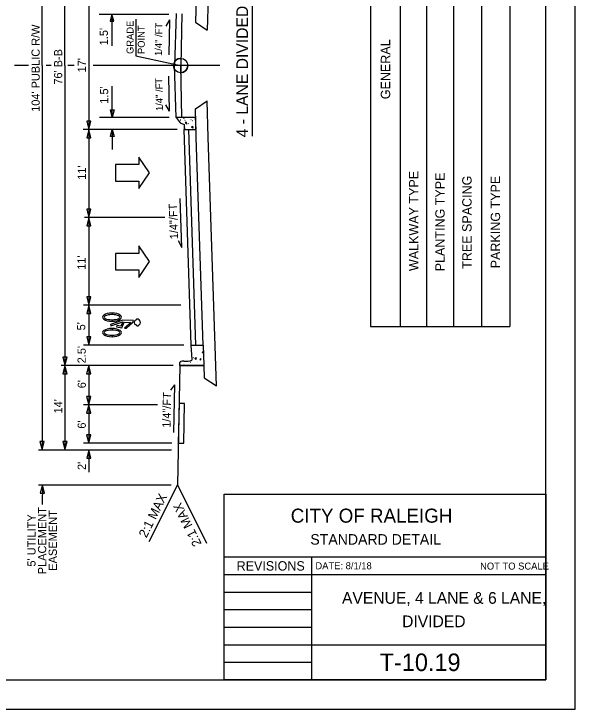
# Model space of a CAD drawing. Extents: x 0 to 8.5, y 0 to 11.
# Drawn here: x 3.7 to 8.5, y 0 to 5.94 of the extents above; entities that cross this region are included whole.
import ezdxf

# ---------------------------------------------------------------- set-up
doc = ezdxf.new("R2010")
doc.units = 0
for name, color, linetype in [('Level 2', 7, 'Continuous'), ('Level 21', 7, 'Continuous'), ('Level 22', 7, 'Continuous'), ('Level 23', 7, 'Continuous'), ('MARK BICYCLE SYMBOL CELL', 7, 'Continuous'), ('Old_Level_1', 7, 'Continuous'), ('Old_Level_11', 7, 'Continuous'), ('PROP LANE ARROW CELL', 7, 'Continuous'), ('Prop Shade Light', 7, 'Continuous'), ('SHEET BORDER', 7, 'Continuous'), ('SHEET NOTES', 7, 'Continuous'), ('SHEET TITLE BLOCK LINE', 7, 'Continuous'), ('SHEET TITLE BLOCK TEXT', 7, 'Continuous'), ('SHEET TRIM BORDER', 7, 'Continuous'), ('Typical Pavement Slope Information CELL', 7, 'Continuous')]:
    doc.layers.add(name, color=color, linetype=linetype)

msp = doc.modelspace()

# ---------------------------------------------------------------- linework, layer by layer
at = {"layer": 'Level 2'}
msp.add_line((5.7386, 6.0451), (5.7386, 4.8951), dxfattribs=at)
at = {"layer": 'Level 22'}
for p, q in [((5.1374, 5.9409), (5.1278, 5.5)), ((5.1319, 5.6877), (5.1319, 5.6877)), ((5.1319, 5.6877), (5.1319, 5.6877)), ((5.1278, 5.5611), (5.1278, 5.5)), ((5.1278, 5.5), (5.0667, 5.5)), ((5.1278, 5.5), (5.1278, 5.4389)), ((5.1889, 5.5), (5.1278, 5.5)), ((5.1374, 5.0591), (5.1278, 5.5)), ((5.1319, 5.3123), (5.1319, 5.3123))]:
    msp.add_line(p, q, dxfattribs=at)
msp.add_circle((5.1278, 5.4999), 0.0611, dxfattribs=at)
for start, end in [(90, 180), (270, 0)]:
    msp.add_arc((5.1278, 5.4999), 0.0611, start, end, dxfattribs=at)
at = {"layer": 'Level 23'}
for p, q in [((5.1388, 3.9439), (5.1241, 4.3629)), ((5.1064, 4.0057), (5.1388, 3.9439)), ((5.0738, 2.7708), (5.0411, 2.7251)), ((5.0738, 2.7708), (5.0657, 2.3647))]:
    msp.add_line(p, q, dxfattribs=at)
at = {"layer": 'MARK BICYCLE SYMBOL CELL'}
for p, q in [((4.5405, 3.3845), (4.5405, 3.3714)), ((4.5405, 3.3845), (4.5405, 3.3714)), ((4.5405, 3.3275), (4.5405, 3.3143)), ((4.5405, 3.3275), (4.5405, 3.3143)), ((4.7526, 3.3269), (4.7526, 3.3351)), ((4.7526, 3.3269), (4.7526, 3.3351)), ((4.6344, 3.325), (4.527, 3.2872)), ((4.527, 3.2872), (4.5299, 3.2747)), ((4.5312, 3.2751), (4.6324, 3.3107)), ((4.582, 3.2794), (4.5793, 3.2669)), ((4.6161, 3.2721), (4.582, 3.2794)), ((4.6324, 3.3107), (4.6161, 3.2721)), ((4.6237, 3.2574), (4.6449, 3.3077)), ((4.724, 3.3197), (4.6344, 3.325)), ((4.6449, 3.3077), (4.7035, 3.3042)), ((4.7035, 3.3042), (4.6483, 3.2547)), ((4.6649, 3.2547), (4.719, 3.3028)), ((4.719, 3.3028), (4.724, 3.3197)), ((4.7526, 3.2745), (4.7526, 3.2827)), ((4.7526, 3.2745), (4.7526, 3.2827)), ((4.5405, 3.2529), (4.5405, 3.2398)), ((4.5405, 3.2529), (4.5405, 3.2398)), ((4.5793, 3.2669), (4.6237, 3.2574)), ((4.6483, 3.2547), (4.6649, 3.2547)), ((4.5405, 3.1959), (4.5405, 3.1828)), ((4.5405, 3.1959), (4.5405, 3.1828))]:
    msp.add_line(p, q, dxfattribs=at)
for radius, start, end in [(0.0303, 270.00002, 90.00002), (0.0303, 270.00002, 90.00002), (0.0221, 90.00002, 270.00002)]:
    msp.add_arc((4.7526, 3.3048), radius, start, end, dxfattribs=at)
for centre, major_axis, ratio, start_param, end_param in [((4.5405, 3.3494), (-0.0804, 0), 0.435841, 4.712389, 7.853982), ((4.5405, 3.3494), (-0.0673, 0), 0.325967, 4.712389, 7.853982), ((4.5405, 3.3494), (-0.0804, 0), 0.435841, 1.570796, 4.712389), ((4.5405, 3.3494), (-0.0673, 0), 0.325967, 1.570796, 4.712389), ((4.5405, 3.2178), (-0.0804, 0), 0.435841, 4.712389, 7.853982), ((4.5405, 3.2178), (-0.0673, 0), 0.325967, 4.712389, 7.853982), ((4.5405, 3.2178), (-0.0804, 0), 0.435841, 1.570796, 4.712389), ((4.5405, 3.2178), (-0.0673, 0), 0.325967, 1.570796, 4.712389)]:
    msp.add_ellipse(centre, major_axis=major_axis, ratio=ratio, start_param=start_param, end_param=end_param, dxfattribs=at)
at = {"layer": 'Old_Level_1'}
for p, q in [((5.2612, 6.114), (5.2533, 5.8693)), ((5.3636, 6.114), (5.3535, 5.8025)), ((5.088, 5.9434), (5.0744, 5.4998)), ((5.2533, 5.8693), (5.3535, 5.8025)), ((5.088, 5.0561), (5.0744, 5.4998)), ((5.2533, 5.1302), (5.3535, 5.1971)), ((5.3636, 4.8855), (5.3535, 5.1971)), ((5.2612, 4.8855), (5.2533, 5.1302)), ((5.1251, 5.0306), (5.1222, 5.0312)), ((5.1268, 5.0364), (5.124, 5.037)), ((5.1651, 5.0312), (5.1622, 5.0315)), ((5.1948, 5.0041), (5.1928, 5.0032)), ((5.2165, 5.0353), (5.2136, 5.0353)), ((5.2308, 5.0278), (5.228, 5.0278)), ((5.2165, 3.111), (5.1566, 4.9538)), ((5.1655, 4.9615), (5.1633, 4.9624)), ((5.2575, 3.111), (5.1976, 4.9538)), ((5.3189, 3.111), (5.2612, 4.8855)), ((5.4326, 2.7623), (5.3636, 4.8855)), ((5.1545, 2.9745), (5.1912, 2.9749)), ((5.2403, 3.0021), (5.2381, 3.0023)), ((5.12, 2.9371), (5.0997, 1.9169)), ((5.12, 2.9366), (5.12, 2.9616)), ((5.3246, 2.9366), (5.12, 2.9366)), ((5.12, 2.9366), (5.1542, 2.9366)), ((5.1309, 2.969), (5.1299, 2.969)), ((5.1563, 2.9388), (5.1538, 2.9388)), ((5.1542, 2.9366), (5.3246, 2.9366)), ((5.2122, 2.9609), (5.2097, 2.9609)), ((5.2723, 2.9669), (5.2701, 2.9669)), ((5.3235, 2.969), (5.3216, 2.969)), ((5.3246, 2.9366), (5.3288, 2.8315)), ((5.3288, 2.8315), (5.4326, 2.7623)), ((5.0997, 1.9169), (4.856, 1.4295)), ((5.0997, 1.9169), (5.3491, 1.4179))]:
    msp.add_line(p, q, dxfattribs=at)
for points in [[(5.088, 5.0561), (5.1237, 5.0118), (5.1566, 4.9959), (5.1566, 4.9538), (5.259, 4.9538), (5.2557, 5.0561)], [(5.1781, 5.0125), (5.1656, 5.0131), (5.1789, 4.9995)], [(5.2303, 4.966), (5.2202, 4.9734), (5.2298, 4.9819)]]:
    msp.add_lwpolyline(points, close=True, dxfattribs=at)
for points in [[(5.1487, 5.0561), (5.1565, 5.0481), (5.156, 5.0561)], [(5.3189, 3.111), (5.3246, 2.9366), (5.1542, 2.9366), (5.12, 2.9366), (5.1201, 2.9616)], [(5.2256, 2.9883), (5.2165, 3.111), (5.3189, 3.111)], [(5.3212, 3.0412), (5.3122, 3.0478), (5.3207, 3.0554)], [(5.2579, 2.9868), (5.2485, 2.9954), (5.2591, 3.0053), (5.2579, 2.9868)], [(5.2999, 2.9856), (5.2985, 2.9968), (5.2921, 2.9873), (5.2999, 2.9856)], [(5.291, 2.9366), (5.2942, 2.9396), (5.294, 2.9366)]]:
    msp.add_lwpolyline(points, dxfattribs=at)
for centre, major_axis, start_param, end_param in [((5.1556, 2.9616), (-0.0356, 0), 4.744401, 6.283185), ((5.1901, 2.9878), (0.0356, 0), 4.744378, 6.315174)]:
    msp.add_ellipse(centre, major_axis=major_axis, ratio=0.362757, start_param=start_param, end_param=end_param, dxfattribs=at)
at = {"layer": 'Old_Level_11'}
for p, q in [((3.9424, 5.5), (3.9424, 8.7842)), ((4.1383, 5.5), (4.1383, 8.7842)), ((4.3431, 6.046), (4.3431, 4.954)), ((4.4319, 5.9404), (5.0271, 5.9404)), ((4.5396, 5.9404), (4.5396, 5.6694)), ((4.7441, 5.8968), (4.744, 5.5833)), ((4.744, 5.5833), (5.1271, 5.5017)), ((3.8261, 5.5), (3.7066, 5.5)), ((3.9424, 5.5), (3.9424, 2.2158)), ((4.0195, 5.5), (3.9777, 5.5)), ((4.1383, 5.5), (4.1383, 2.9369)), ((4.2162, 5.5), (4.1625, 5.5)), ((5.463, 5.5), (4.3792, 5.5)), ((4.5425, 5.0596), (4.5425, 5.3249)), ((4.4348, 5.0596), (5.0299, 5.0595)), ((4.1383, 4.954), (4.1383, 2.2158)), ((5.0972, 4.954), (4.2944, 4.954)), ((4.3431, 4.954), (4.3431, 4.2032)), ((4.5425, 4.954), (4.5425, 4.7816)), ((4.9935, 4.202), (4.3043, 4.202)), ((4.3431, 4.2032), (4.3431, 3.1112)), ((5.1299, 3.4525), (4.2981, 3.4525)), ((5.1547, 3.1112), (4.2972, 3.1112)), ((5.0638, 2.9369), (4.105, 2.9369)), ((4.3414, 2.9369), (4.3414, 2.5994)), ((4.9281, 2.5994), (4.2972, 2.5994)), ((4.3414, 2.5994), (4.3414, 2.2722)), ((5.0526, 2.2722), (4.2972, 2.2722)), ((3.9115, 2.2158), (5.0498, 2.2158)), ((4.3431, 2.2146), (4.3431, 2.0245)), ((3.9115, 1.9169), (5.0451, 1.9169)), ((3.9449, 1.9168), (3.9443, 1.7476))]:
    msp.add_line(p, q, dxfattribs=at)
for points in [[(4.555, 5.8788), (4.5396, 5.9404), (4.5242, 5.8788)], [(4.5579, 5.1211), (4.5425, 5.0596), (4.5271, 5.1211)], [(4.3254, 5.0248), (4.3431, 4.954), (4.3608, 5.0248)], [(4.3608, 4.8832), (4.3431, 4.954), (4.3254, 4.8832)], [(4.5271, 4.8924), (4.5425, 4.954), (4.5579, 4.8924)], [(4.3254, 4.2727), (4.3431, 4.202), (4.3608, 4.2727)], [(4.3608, 4.1312), (4.3431, 4.202), (4.3254, 4.1312)], [(4.3254, 3.5233), (4.3431, 3.4525), (4.3608, 3.5233)], [(4.3608, 3.3817), (4.3431, 3.4525), (4.3254, 3.3817)], [(4.3254, 3.182), (4.3431, 3.1112), (4.3608, 3.182)], [(4.1206, 3.0076), (4.1383, 2.9369), (4.156, 3.0076)], [(4.156, 2.8661), (4.1383, 2.9369), (4.1206, 2.8661)], [(4.3591, 2.8661), (4.3414, 2.9369), (4.3237, 2.8661)], [(4.3237, 2.6702), (4.3414, 2.5994), (4.3591, 2.6702)], [(4.3591, 2.5286), (4.3414, 2.5994), (4.3237, 2.5286)], [(4.3237, 2.343), (4.3414, 2.2722), (4.3591, 2.343)], [(3.9247, 2.2866), (3.9424, 2.2158), (3.9601, 2.2866)], [(4.1206, 2.2866), (4.1383, 2.2158), (4.156, 2.2866)], [(4.3608, 2.1438), (4.3431, 2.2146), (4.3254, 2.1438)], [(3.9626, 1.846), (3.9449, 1.9168), (3.9272, 1.846)]]:
    msp.add_lwpolyline(points, close=True, dxfattribs=at)
at = {"layer": 'PROP LANE ARROW CELL'}
for points in [[(4.7704, 4.7177), (4.7704, 4.6535), (4.5708, 4.6535), (4.5708, 4.5124), (4.7704, 4.5124), (4.7704, 4.4483), (4.8622, 4.5843), (4.7704, 4.7177)], [(4.7704, 3.9591), (4.7704, 3.895), (4.5708, 3.895), (4.5708, 3.7538), (4.7704, 3.7538), (4.7704, 3.6897), (4.8622, 3.8257), (4.7704, 3.9591)]]:
    msp.add_lwpolyline(points, dxfattribs=at)
at = {"layer": 'Prop Shade Light'}
msp.add_lwpolyline([(5.1135, 2.611), (5.1068, 2.2718), (5.1544, 2.2713), (5.1612, 2.611)], close=True, dxfattribs=at)
at = {"layer": 'SHEET BORDER'}
msp.add_lwpolyline([(8.25, 10.75), (0.25, 10.75), (0.25, 0.25), (8.25, 0.25)], close=True, dxfattribs=at)
at = {"layer": 'SHEET NOTES'}
for p, q in [((6.7507, 7.9712), (6.7507, 3.2689)), ((7.0041, 7.9712), (7.0041, 3.2689)), ((7.2283, 7.9712), (7.2283, 3.2689)), ((7.4596, 7.9712), (7.4596, 3.2689)), ((7.7009, 7.9712), (7.7009, 3.2689)), ((7.9422, 7.9712), (7.9422, 3.2689)), ((6.7507, 3.2689), (7.9422, 3.2689))]:
    msp.add_line(p, q, dxfattribs=at)
at = {"layer": 'SHEET TITLE BLOCK LINE'}
for p, q in [((5.5002, 1.2999), (8.25, 1.2999)), ((6.2501, 0.25), (6.2501, 1.2999)), ((5.5002, 1.1499), (8.25, 1.1499)), ((5.5002, 0.9999), (6.2501, 0.9999)), ((5.5002, 0.85), (6.2501, 0.85)), ((5.5002, 0.7), (6.2501, 0.7)), ((5.5002, 0.55), (6.2501, 0.55)), ((6.2501, 0.55), (8.25, 0.55)), ((5.5002, 0.4), (6.2501, 0.4)), ((5.5002, 0.25), (8.25, 0.25))]:
    msp.add_line(p, q, dxfattribs=at)
msp.add_lwpolyline([(8.25, 0.25), (5.5002, 0.25), (5.5002, 1.8359), (8.25, 1.8359)], close=True, dxfattribs=at)
at = {"layer": 'SHEET TRIM BORDER'}
msp.add_lwpolyline([(8.5, 11), (0, 11), (0, 0), (8.5, 0)], close=True, dxfattribs=at)
at = {"layer": 'Typical Pavement Slope Information CELL'}
for p, q in [((5.0332, 5.891), (4.9999, 5.8359)), ((5.0332, 5.891), (5.0273, 5.5913)), ((5.0332, 5.1091), (5.0267, 5.4094)), ((5.0332, 5.1091), (4.9999, 5.1642))]:
    msp.add_line(p, q, dxfattribs=at)

# ---------------------------------------------------------------- texts
at = {"layer": 'Level 2'}
msp.add_text('4 - LANE DIVIDED', height=0.100219, rotation=90, dxfattribs=at).set_placement((5.704, 4.8864))
at = {"layer": 'Level 21'}
for s, height, rotation, p in [("104' PUBLIC R/W", 0.07, 90, (3.9222, 5.1047)), ("76' B-B", 0.07, 90, (4.1149, 5.3369)), ("17'", 0.07, 90, (4.3169, 5.4419)), ("11'", 0.07, 90, (4.3179, 4.5244)), ('1/4"/FT', 0.07, 92.01118, (5.1057, 4.017)), ("11'", 0.07, 90, (4.3148, 3.7544)), ("5'", 0.07, 90, (4.3115, 3.2367)), ("6'", 0.07, 90, (4.3168, 2.742)), ('1/4"/FT', 0.07, 88.85773, (5.0403, 2.403)), ("6'", 0.07, 90, (4.3163, 2.3966)), ('2:1 MAX', 0.07821, 63.43495, (4.8344, 1.4578)), ('2:1 MAX', 0.07821, 116.56505, (5.3089, 1.4131))]:
    msp.add_text(s, height=height, rotation=rotation, dxfattribs=at).set_placement(p)
at = {"layer": 'Old_Level_11'}
for s, height, rotation, p in [('GRADE', 0.05983, 89.99789, (4.7246, 5.599)), ('POINT', 0.05983, 89.99789, (4.8205, 5.5985)), ("1.5'", 0.07039, 90, (4.5051, 5.6727)), ("1.5'", 0.07039, 90, (4.508, 5.1736)), ("2.5'", 0.07, 90, (4.3158, 2.9551)), ("14'", 0.07, 90, (4.1149, 2.5264)), ("2'", 0.07, 90, (4.3169, 2.0436)), ('PLACEMENT', 0.07039, 90, (3.9779, 1.1517)), ('EASEMENT', 0.07039, 90, (4.069, 1.1822)), ("5' UTILITY", 0.07039, 90, (3.8868, 1.2179))]:
    msp.add_text(s, height=height, rotation=rotation, dxfattribs=at).set_placement(p)
at = {"layer": 'SHEET NOTES'}
for s, p in [('GENERAL', (6.9188, 5.2123)), ('WALKWAY TYPE', (7.1602, 3.7437)), ('PLANTING TYPE', (7.3846, 3.7413)), ('TREE SPACING', (7.6149, 3.7626)), ('PARKING TYPE', (7.8588, 3.7671))]:
    msp.add_text(s, height=0.08, rotation=90, dxfattribs=at).set_placement(p)
at = {"layer": 'SHEET TITLE BLOCK TEXT'}
for s, height, p in [('CITY OF RALEIGH', 0.12, (6.0686, 1.5932)), ('STANDARD DETAIL', 0.09, (6.2364, 1.4053)), ('REVISIONS', 0.08, (5.6059, 1.184)), ('DATE: 8/1/18', 0.06, (6.2796, 1.195)), ('NOT TO SCALE', 0.06, (7.6877, 1.1922)), ('AVENUE, 4 LANE & 6 LANE,', 0.100002, (6.5069, 0.9)), ('DIVIDED', 0.1, (7.0208, 0.7)), ('T-10.19', 0.15, (6.8292, 0.325))]:
    msp.add_text(s, height=height, dxfattribs=at).set_placement(p)
at = {"layer": 'Typical Pavement Slope Information CELL'}
for rotation, p in [(88.85215, (4.9661, 5.5812)), (91.14785, (4.9763, 5.1122))]:
    msp.add_text('1/4" /FT', height=0.06, rotation=rotation, dxfattribs=at).set_placement(p)

doc.saveas('drawing.dxf')
